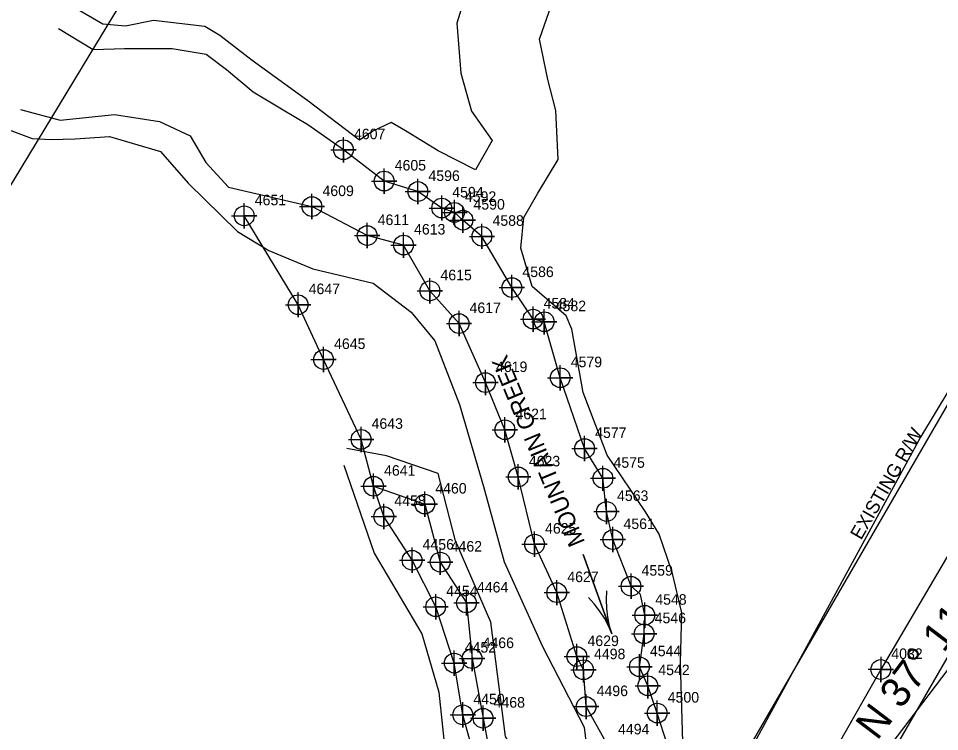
# Model space of a CAD drawing. Extents: x 1653123 to 1656194, y 596584 to 600233.
# Drawn here: x 1653591.7 to 1653810.3, y 598109.7 to 598278.9 of the extents above; entities that cross this region are included whole.
import ezdxf

# ---------------------------------------------------------------- set-up
doc = ezdxf.new("R2010")
doc.units = 0
for name, color, linetype in [('Exist Horizontal Alignment', 7, 'Continuous'), ('Exist Horizontal Baseline Alignment', 7, 'Continuous'), ('Exist Horizontal Baseline Alignment Direction Label', 7, 'Continuous'), ('Exist Hydro Jurisdictional Stream or Body of Water', 7, 'Continuous'), ('Exist Hydro River Flow Arrow CELL', 7, 'Continuous'), ('Exist Hydro Stream or Body of Water Cogo Number', 7, 'Continuous'), ('Exist Hydro Stream or Body of Water Text', 7, 'Continuous'), ('Exist Right of Way Line', 7, 'Continuous'), ('Exist Right of Way Line Text', 7, 'Continuous'), ('Exist Roads EOP Cogo Point CELL', 7, 'Continuous'), ('Exist Vegetation Woods Line', 7, 'Continuous'), ('Prop Conc Shoulder Berm Gutter', 7, 'Continuous'), ('Prop Easement Construction Station Offsets', 7, 'Continuous'), ('Prop Guardrail', 7, 'Continuous'), ('Prop Guardrail Anchor Unit CELL', 7, 'Continuous'), ('Prop Horizontal Alignment', 7, 'Continuous')]:
    doc.layers.add(name, color=color, linetype=linetype)

msp = doc.modelspace()

# ---------------------------------------------------------------- linework, layer by layer
at = {"layer": 'Exist Horizontal Alignment'}
msp.add_line((1653731.56, 597988.04), (1653850.42, 598193.46), dxfattribs=at)
at = {"layer": 'Exist Horizontal Baseline Alignment'}
msp.add_line((1653732.12, 598018.79), (1653909.76, 598252.91), dxfattribs=at)
at = {"layer": 'Exist Hydro Jurisdictional Stream or Body of Water'}
for points in [[(1653668.84, 598247.75), (1653660.38, 598253.66), (1653654.51, 598257.13), (1653647.43, 598261.44), (1653641.07, 598266.71), (1653636.26, 598270.31), (1653628.22, 598271.66), (1653616.92, 598271.67), (1653609.44, 598271.46), (1653601.2, 598276.44)], [(1653592.2, 598257.3), (1653601.63, 598254.76), (1653614.48, 598256.07), (1653625.18, 598254.45), (1653632.46, 598251.08), (1653636.22, 598244.73), (1653641.58, 598238.9), (1653661.37, 598234.26)], [(1653739.35, 598142.28), (1653737.07, 598144.22), (1653732.79, 598155.28), (1653731.26, 598161.94), (1653730.42, 598169.81), (1653726.06, 598176.87), (1653720.27, 598193.67), (1653716.47, 598206.96), (1653713.82, 598207.58), (1653708.8, 598215.05), (1653701.71, 598227.21), (1653697.19, 598231.05), (1653695.16, 598232.89), (1653692.16, 598233.93), (1653686.51, 598237.84), (1653678.5, 598240.32), (1653668.84, 598247.75)], [(1653724.25, 598127.52), (1653719.45, 598142.69), (1653714.18, 598154.19), (1653710.33, 598170.14), (1653707.16, 598181.32), (1653702.54, 598192.52), (1653696.26, 598206.51), (1653689.36, 598214.28), (1653683.09, 598225.14), (1653674.47, 598227.39), (1653661.37, 598234.26)], [(1653714.69, 598088.49), (1653716.57, 598082.14), (1653721.28, 598074.07), (1653726.41, 598067), (1653731.18, 598063.58), (1653732.89, 598067.69), (1653733.02, 598076.06), (1653731.56, 598088.25), (1653732.11, 598095.88), (1653731.5, 598106.57), (1653726.42, 598115.65), (1653725.8, 598124.41), (1653724.25, 598127.52)], [(1653752.6, 598048.33), (1653751.11, 598051.03), (1653748.62, 598061.5), (1653747.51, 598068.2), (1653746.66, 598076.93), (1653747.24, 598081.73), (1653747.99, 598099.4), (1653743.29, 598114.12), (1653741.06, 598120.62)]]:
    msp.add_lwpolyline(points, dxfattribs=at)
at = {"layer": 'Exist Hydro River Flow Arrow CELL'}
msp.add_line((1653729.11, 598142.31), (1653729.11, 598142.31), dxfattribs=at)
msp.add_lwpolyline([(1653731.26, 598143.09), (1653731.16, 598141.04), (1653731.24, 598138.97), (1653731.48, 598136.89), (1653731.89, 598134.86), (1653732.52, 598132.91), (1653725.7, 598151.71), (1653732.52, 598132.91), (1653731.75, 598134.81), (1653730.76, 598136.63), (1653729.61, 598138.38), (1653728.34, 598140.02), (1653726.96, 598141.53)], dxfattribs=at)
at = {"layer": 'Exist Right of Way Line'}
msp.add_line((1653705.6, 598003.07), (1653824.45, 598208.48), dxfattribs=at)
at = {"layer": 'Exist Roads EOP Cogo Point CELL'}
msp.add_lwpolyline([(1653796.34, 598127.46), (1653796.34, 598121.46), (1653796.34, 598124.46), (1653799.34, 598124.46), (1653793.34, 598124.46)], dxfattribs=at)
msp.add_circle((1653796.34, 598124.46), 2.34, dxfattribs=at)
at = {"layer": 'Exist Vegetation Woods Line'}
for points in [[(1653700.4, 598292.89), (1653695.73, 598277.79), (1653696.69, 598265.95), (1653699.23, 598256.88), (1653704.16, 598249.97), (1653700.15, 598242.96), (1653691.3, 598247.51), (1653683.55, 598252.2), (1653680.16, 598254.25), (1653675.82, 598252.14), (1653672.66, 598249.99), (1653660.38, 598259.38), (1653647.16, 598268.9), (1653639.51, 598274.81), (1653635.96, 598276.97), (1653623.77, 598278.41), (1653617.09, 598277.04), (1653611.71, 598277.55), (1653605.33, 598281.28)], [(1653749.48, 598104.57), (1653748.79, 598126.12), (1653749.12, 598137.88), (1653746.81, 598147.59), (1653743.75, 598156.58), (1653740.49, 598161.86), (1653731.38, 598175.29), (1653725.72, 598190.18), (1653723.04, 598205.19), (1653721.68, 598208.36), (1653713.59, 598215.28), (1653710.93, 598224.39), (1653711.62, 598231.7), (1653715, 598237.47), (1653719.8, 598245.4), (1653719.22, 598257.04), (1653717.32, 598264.41), (1653715.32, 598273.97), (1653719.31, 598285.4)], [(1653858.45, 598266.95), (1653805.74, 598179.56), (1653755.09, 598086.35)], [(1653589.26, 598252.57), (1653594.94, 598250.38), (1653599.48, 598250.17), (1653605.18, 598250.35), (1653613.31, 598250.89), (1653625.44, 598247.35), (1653631.98, 598239.83), (1653643.71, 598228.37), (1653651.15, 598223.87), (1653661.59, 598219.54), (1653675.88, 598216.14), (1653684.87, 598209.26), (1653690.52, 598202.39), (1653696.35, 598187.36), (1653702.04, 598167.88), (1653707, 598150), (1653716.09, 598129.89), (1653725.93, 598110.77), (1653727.5, 598097.56), (1653724.04, 598088.27), (1653721.38, 598083.89)], [(1653721.38, 598083.89), (1653707.31, 598108.61), (1653703.8, 598135.73), (1653695.45, 598154.98), (1653691.35, 598170.96), (1653679.08, 598175.13), (1653669.66, 598176.85)], [(1653668.95, 598172.91), (1653676.12, 598152.03), (1653687.47, 598132.91), (1653691.49, 598119.1), (1653693.18, 598102.65), (1653700.53, 598089.05), (1653706.13, 598085.81), (1653707.72, 598067.81), (1653717.78, 598061.15)]]:
    msp.add_lwpolyline(points, dxfattribs=at)
at = {"layer": 'Prop Conc Shoulder Berm Gutter'}
msp.add_lwpolyline([(1653963.23, 598414.46), (1653946.12, 598382.23), (1653936.11, 598363.27), (1653937.56, 598362.44), (1653921.88, 598335.54), (1653898.59, 598297.25), (1653874.99, 598257.81), (1653851, 598217.57), (1653836.48, 598192.61), (1653818.81, 598162.68), (1653796.34, 598124.46), (1653774.27, 598085.68), (1653759.99, 598060.76), (1653759, 598059.62)], dxfattribs=at)
at = {"layer": 'Prop Easement Construction Station Offsets'}
for points in [[(1653675.98, 598167.93), (1653673.01, 598179.05), (1653664.12, 598197.98), (1653658.08, 598211), (1653645.3, 598232.07)], [(1653675.98, 598167.93), (1653688.13, 598163.69), (1653691.79, 598149.93), (1653698.02, 598140.24), (1653699.36, 598127.04), (1653701.97, 598112.91), (1653704.08, 598101.76), (1653706.16, 598098.01), (1653714.69, 598088.49)], [(1653711.13, 598085.34), (1653703.68, 598096.37), (1653699.81, 598104.28), (1653697.16, 598113.71), (1653695.12, 598125.97), (1653690.72, 598139.34), (1653685.12, 598150.38), (1653678.42, 598160.74), (1653675.98, 598167.93)], [(1653741.06, 598120.62), (1653739.06, 598125.11), (1653740.19, 598132.94), (1653740.33, 598137.33), (1653739.35, 598142.28)]]:
    msp.add_lwpolyline(points, dxfattribs=at)
at = {"layer": 'Prop Guardrail'}
msp.add_lwpolyline([(1653903.59, 597776.41), (1653711.71, 597877.2), (1653696.02, 597886.41), (1653672.02, 597900.5), (1653657.82, 597908.84), (1653581.92, 597953.42), (1653467.13, 598020.82), (1653530, 598138.71), (1653544.59, 598164.59), (1653608.47, 598270), (1653650, 598338.52), (1653727.49, 598470), (1653919.05, 598343.12), (1654024.03, 598279.05), (1654101.16, 598231.66), (1654152.92, 598207.08), (1653974.95, 597910)], close=True, dxfattribs=at)
at = {"layer": 'Prop Guardrail Anchor Unit CELL'}
for points in [[(1653665.84, 598247.75), (1653671.84, 598247.75), (1653668.84, 598247.75), (1653668.84, 598244.75), (1653668.84, 598250.75)], [(1653675.5, 598240.32), (1653681.5, 598240.32), (1653678.5, 598240.32), (1653678.5, 598237.32), (1653678.5, 598243.32)], [(1653683.51, 598237.84), (1653689.51, 598237.84), (1653686.51, 598237.84), (1653686.51, 598234.84), (1653686.51, 598240.84)], [(1653658.37, 598234.26), (1653664.37, 598234.26), (1653661.37, 598234.26), (1653661.37, 598231.26), (1653661.37, 598237.26)], [(1653689.16, 598233.93), (1653695.16, 598233.93), (1653692.16, 598233.93), (1653692.16, 598230.93), (1653692.16, 598236.93)], [(1653692.16, 598232.89), (1653698.16, 598232.89), (1653695.16, 598232.89), (1653695.16, 598229.89), (1653695.16, 598235.89)], [(1653642.3, 598232.07), (1653648.3, 598232.07), (1653645.3, 598232.07), (1653645.3, 598229.07), (1653645.3, 598235.07)], [(1653694.19, 598231.05), (1653700.19, 598231.05), (1653697.19, 598231.05), (1653697.19, 598228.05), (1653697.19, 598234.05)], [(1653671.47, 598227.39), (1653677.47, 598227.39), (1653674.47, 598227.39), (1653674.47, 598224.39), (1653674.47, 598230.39)], [(1653698.71, 598227.21), (1653704.71, 598227.21), (1653701.71, 598227.21), (1653701.71, 598224.21), (1653701.71, 598230.21)], [(1653680.09, 598225.14), (1653686.09, 598225.14), (1653683.09, 598225.14), (1653683.09, 598222.14), (1653683.09, 598228.14)], [(1653705.8, 598215.05), (1653711.8, 598215.05), (1653708.8, 598215.05), (1653708.8, 598212.05), (1653708.8, 598218.05)], [(1653686.36, 598214.28), (1653692.36, 598214.28), (1653689.36, 598214.28), (1653689.36, 598211.28), (1653689.36, 598217.28)], [(1653655.08, 598211), (1653661.08, 598211), (1653658.08, 598211), (1653658.08, 598208), (1653658.08, 598214)], [(1653693.26, 598206.51), (1653699.26, 598206.51), (1653696.26, 598206.51), (1653696.26, 598203.51), (1653696.26, 598209.51)], [(1653710.82, 598207.58), (1653716.82, 598207.58), (1653713.82, 598207.58), (1653713.82, 598204.58), (1653713.82, 598210.58)], [(1653713.47, 598206.96), (1653719.47, 598206.96), (1653716.47, 598206.96), (1653716.47, 598203.96), (1653716.47, 598209.96)], [(1653661.12, 598197.98), (1653667.12, 598197.98), (1653664.12, 598197.98), (1653664.12, 598194.98), (1653664.12, 598200.98)], [(1653717.27, 598193.67), (1653723.27, 598193.67), (1653720.27, 598193.67), (1653720.27, 598190.67), (1653720.27, 598196.67)], [(1653699.54, 598192.52), (1653705.54, 598192.52), (1653702.54, 598192.52), (1653702.54, 598189.52), (1653702.54, 598195.52)], [(1653704.16, 598181.32), (1653710.16, 598181.32), (1653707.16, 598181.32), (1653707.16, 598178.32), (1653707.16, 598184.32)], [(1653670.01, 598179.05), (1653676.01, 598179.05), (1653673.01, 598179.05), (1653673.01, 598176.05), (1653673.01, 598182.05)], [(1653723.06, 598176.87), (1653729.06, 598176.87), (1653726.06, 598176.87), (1653726.06, 598173.87), (1653726.06, 598179.87)], [(1653707.33, 598170.14), (1653713.33, 598170.14), (1653710.33, 598170.14), (1653710.33, 598167.14), (1653710.33, 598173.14)], [(1653727.42, 598169.81), (1653733.42, 598169.81), (1653730.42, 598169.81), (1653730.42, 598166.81), (1653730.42, 598172.81)], [(1653672.98, 598167.93), (1653678.98, 598167.93), (1653675.98, 598167.93), (1653675.98, 598164.93), (1653675.98, 598170.93)], [(1653685.13, 598163.69), (1653691.13, 598163.69), (1653688.13, 598163.69), (1653688.13, 598160.69), (1653688.13, 598166.69)], [(1653675.42, 598160.74), (1653681.42, 598160.74), (1653678.42, 598160.74), (1653678.42, 598157.74), (1653678.42, 598163.74)], [(1653728.26, 598161.94), (1653734.26, 598161.94), (1653731.26, 598161.94), (1653731.26, 598158.94), (1653731.26, 598164.94)], [(1653711.18, 598154.19), (1653717.18, 598154.19), (1653714.18, 598154.19), (1653714.18, 598151.19), (1653714.18, 598157.19)], [(1653729.79, 598155.28), (1653735.79, 598155.28), (1653732.79, 598155.28), (1653732.79, 598152.28), (1653732.79, 598158.28)], [(1653682.12, 598150.38), (1653688.12, 598150.38), (1653685.12, 598150.38), (1653685.12, 598147.38), (1653685.12, 598153.38)], [(1653688.79, 598149.93), (1653694.79, 598149.93), (1653691.79, 598149.93), (1653691.79, 598146.93), (1653691.79, 598152.93)], [(1653734.07, 598144.22), (1653740.07, 598144.22), (1653737.07, 598144.22), (1653737.07, 598141.22), (1653737.07, 598147.22)], [(1653716.45, 598142.69), (1653722.45, 598142.69), (1653719.45, 598142.69), (1653719.45, 598139.69), (1653719.45, 598145.69)], [(1653687.72, 598139.34), (1653693.72, 598139.34), (1653690.72, 598139.34), (1653690.72, 598136.34), (1653690.72, 598142.34)], [(1653695.02, 598140.24), (1653701.02, 598140.24), (1653698.02, 598140.24), (1653698.02, 598137.24), (1653698.02, 598143.24)], [(1653737.33, 598137.33), (1653743.33, 598137.33), (1653740.33, 598137.33), (1653740.33, 598134.33), (1653740.33, 598140.33)], [(1653737.19, 598132.94), (1653743.19, 598132.94), (1653740.19, 598132.94), (1653740.19, 598129.94), (1653740.19, 598135.94)], [(1653721.25, 598127.52), (1653727.25, 598127.52), (1653724.25, 598127.52), (1653724.25, 598124.52), (1653724.25, 598130.52)], [(1653692.12, 598125.97), (1653698.12, 598125.97), (1653695.12, 598125.97), (1653695.12, 598122.97), (1653695.12, 598128.97)], [(1653696.36, 598127.04), (1653702.36, 598127.04), (1653699.36, 598127.04), (1653699.36, 598124.04), (1653699.36, 598130.04)], [(1653722.8, 598124.41), (1653728.8, 598124.41), (1653725.8, 598124.41), (1653725.8, 598121.41), (1653725.8, 598127.41)], [(1653736.06, 598125.11), (1653742.06, 598125.11), (1653739.06, 598125.11), (1653739.06, 598122.11), (1653739.06, 598128.11)], [(1653738.06, 598120.62), (1653744.06, 598120.62), (1653741.06, 598120.62), (1653741.06, 598117.62), (1653741.06, 598123.62)], [(1653723.42, 598115.65), (1653729.42, 598115.65), (1653726.42, 598115.65), (1653726.42, 598112.65), (1653726.42, 598118.65)], [(1653694.16, 598113.71), (1653700.16, 598113.71), (1653697.16, 598113.71), (1653697.16, 598110.71), (1653697.16, 598116.71)], [(1653698.97, 598112.91), (1653704.97, 598112.91), (1653701.97, 598112.91), (1653701.97, 598109.91), (1653701.97, 598115.91)], [(1653740.29, 598114.12), (1653746.29, 598114.12), (1653743.29, 598114.12), (1653743.29, 598111.12), (1653743.29, 598117.12)]]:
    msp.add_lwpolyline(points, dxfattribs=at)
for centre in [(1653668.84, 598247.75), (1653678.5, 598240.32), (1653686.51, 598237.84), (1653661.37, 598234.26), (1653692.16, 598233.93), (1653645.3, 598232.07), (1653695.16, 598232.89), (1653697.19, 598231.05), (1653674.47, 598227.39), (1653701.71, 598227.21), (1653683.09, 598225.14), (1653689.36, 598214.28), (1653708.8, 598215.05), (1653658.08, 598211), (1653713.82, 598207.58), (1653716.47, 598206.96), (1653696.26, 598206.51), (1653664.12, 598197.98), (1653702.54, 598192.52), (1653720.27, 598193.67), (1653707.16, 598181.32), (1653673.01, 598179.05), (1653726.06, 598176.87), (1653710.33, 598170.14), (1653730.42, 598169.81), (1653675.98, 598167.93), (1653688.13, 598163.69), (1653731.26, 598161.94), (1653678.42, 598160.74), (1653732.79, 598155.28), (1653714.18, 598154.19), (1653685.12, 598150.38), (1653691.79, 598149.93), (1653737.07, 598144.22), (1653719.45, 598142.69), (1653690.72, 598139.34), (1653698.02, 598140.24), (1653740.33, 598137.33), (1653740.19, 598132.94), (1653695.12, 598125.97), (1653699.36, 598127.04), (1653724.25, 598127.52), (1653725.8, 598124.41), (1653739.06, 598125.11), (1653741.06, 598120.62), (1653726.42, 598115.65), (1653697.16, 598113.71), (1653701.97, 598112.91), (1653743.29, 598114.12)]:
    msp.add_circle(centre, 2.34, dxfattribs=at)

# ---------------------------------------------------------------- texts
at = {"layer": 'Exist Horizontal Baseline Alignment Direction Label'}
msp.add_text('N 37%%d 11\' 22.0" E', height=7, rotation=52.8105, dxfattribs=at).set_placement((1653795.47, 598107.42))
at = {"layer": 'Exist Hydro Stream or Body of Water Cogo Number'}
for s, p in [('4607', (1653671.34, 598250.25)), ('4605', (1653681, 598242.82)), ('4596', (1653689.01, 598240.34)), ('4609', (1653663.87, 598236.76)), ('4594', (1653694.66, 598236.43)), ('4592', (1653697.66, 598235.39)), ('4651', (1653647.8, 598234.57)), ('4590', (1653699.69, 598233.55)), ('4611', (1653676.97, 598229.89)), ('4588', (1653704.21, 598229.71)), ('4613', (1653685.59, 598227.64)), ('4586', (1653711.3, 598217.55)), ('4615', (1653691.86, 598216.78)), ('4647', (1653660.58, 598213.5)), ('4617', (1653698.76, 598209.01)), ('4584', (1653716.32, 598210.08)), ('4582', (1653718.97, 598209.46)), ('4645', (1653666.62, 598200.48)), ('4579', (1653722.77, 598196.17)), ('4619', (1653705.04, 598195.02)), ('4621', (1653709.66, 598183.82)), ('4643', (1653675.51, 598181.55)), ('4577', (1653728.56, 598179.37)), ('4623', (1653712.83, 598172.64)), ('4575', (1653732.92, 598172.31)), ('4641', (1653678.48, 598170.43)), ('4460', (1653690.63, 598166.19)), ('4458', (1653680.92, 598163.24)), ('4563', (1653733.76, 598164.44)), ('4625', (1653716.68, 598156.69)), ('4561', (1653735.29, 598157.78)), ('4456', (1653687.62, 598152.88)), ('4462', (1653694.29, 598152.43)), ('4559', (1653739.57, 598146.72)), ('4627', (1653721.95, 598145.19)), ('4454', (1653693.22, 598141.84)), ('4464', (1653700.52, 598142.74)), ('4548', (1653742.83, 598139.83)), ('4546', (1653742.69, 598135.44)), ('4452', (1653697.62, 598128.47)), ('4466', (1653701.86, 598129.54)), ('4629', (1653726.75, 598130.02)), ('4498', (1653728.3, 598126.91)), ('4544', (1653741.56, 598127.61)), ('4542', (1653743.56, 598123.12)), ('4496', (1653728.92, 598118.15)), ('4450', (1653699.66, 598116.21)), ('4468', (1653704.47, 598115.41)), ('4500', (1653745.79, 598116.62)), ('4494', (1653734, 598109.07))]:
    msp.add_text(s, height=2.5, dxfattribs=at).set_placement(p)
at = {"layer": 'Exist Hydro Stream or Body of Water Text'}
msp.add_text(' MOUNTAIN CREEK', height=4, rotation=112.6381, dxfattribs=at).set_placement((1653726.78, 598153.28))
at = {"layer": 'Exist Right of Way Line Text'}
msp.add_text('EXISTING R/W', height=3.2, rotation=59.9451, dxfattribs=at).set_placement((1653791.67, 598155.02))
at = {"layer": 'Prop Horizontal Alignment'}
msp.add_text('4032', height=2.5, dxfattribs=at).set_placement((1653798.84, 598126.96))

doc.saveas('drawing.dxf')
